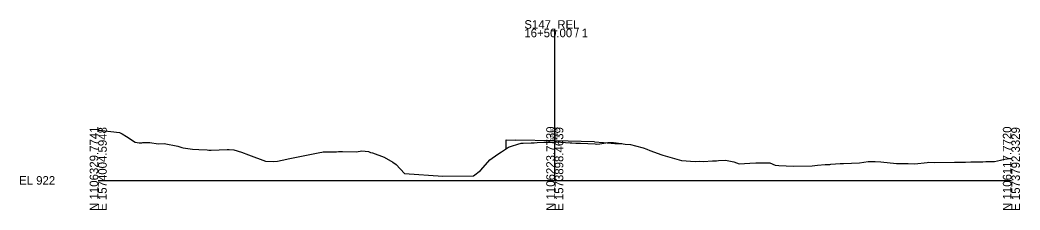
# Model space of a CAD drawing. Extents: x 1557985 to 1558314, y 1113650 to 1118205.
# Drawn here: x 1557985.4 to 1558314, y 1114650.1 to 1114712.4 of the extents above; entities that cross this region are included whole.
import ezdxf

# ---------------------------------------------------------------- set-up
doc = ezdxf.new("R2010")
doc.units = 0
for name, color, linetype in [('RD_GPK_XS_Cell', 7, 'Continuous'), ('RD_XS_EarthShd', 7, 'Continuous'), ('RD_XS_ExGround', 7, 'Continuous'), ('RD_XS_Pave', 7, 'Continuous'), ('RD_XS_TieSlope', 7, 'Continuous'), ('RD_XS_TX_Elev_EX', 7, 'Continuous'), ('RD_XS_TX_Elev_PR', 7, 'Continuous')]:
    doc.layers.add(name, color=color, linetype=linetype)

msp = doc.modelspace()

# ---------------------------------------------------------------- linework, layer by layer
at = {"layer": 'RD_GPK_XS_Cell'}
for p, q in [((1558161.13, 1114659.8), (1558161.13, 1114709.55)), ((1558011.13, 1114659.8), (1558161.13, 1114659.8)), ((1558161.13, 1114659.8), (1558311.13, 1114659.8))]:
    msp.add_line(p, q, dxfattribs=at)
at = {"layer": 'RD_XS_EarthShd'}
for p, q in [((1558145.12, 1114673.06), (1558148.13, 1114673)), ((1558174.13, 1114672.48), (1558177.13, 1114672.24)), ((1558177.13, 1114672.24), (1558180.88, 1114671.94))]:
    msp.add_line(p, q, dxfattribs=at)
at = {"layer": 'RD_XS_ExGround'}
msp.add_lwpolyline([(1558011.13, 1114676.38), (1558011.45, 1114676.32), (1558018.08, 1114675.46), (1558018.99, 1114675.08), (1558020.46, 1114674.21), (1558023.22, 1114672.32), (1558024.54, 1114672.07), (1558025.44, 1114672.14), (1558025.82, 1114672.19), (1558028.04, 1114672.23), (1558030.83, 1114671.78), (1558032.84, 1114671.91), (1558037.34, 1114671.01), (1558038.25, 1114670.67), (1558038.58, 1114670.58), (1558039, 1114670.53), (1558042.11, 1114670.08), (1558044.19, 1114669.96), (1558046.96, 1114669.8), (1558047.46, 1114669.69), (1558048.25, 1114669.69), (1558050.92, 1114669.82), (1558053.51, 1114669.9), (1558054.1, 1114669.89), (1558055.69, 1114669.86), (1558058.18, 1114669.06), (1558060.55, 1114668.17), (1558066.05, 1114666.15), (1558068.66, 1114666.05), (1558070.05, 1114666.12), (1558071.51, 1114666.41), (1558074.05, 1114666.97), (1558083.9, 1114668.95), (1558084.59, 1114669.1), (1558085.07, 1114669.16), (1558086.25, 1114669.18), (1558088.84, 1114669.19), (1558089.45, 1114669.19), (1558090.08, 1114669.24), (1558091.35, 1114669.3), (1558096.01, 1114669.17), (1558097.73, 1114669.45), (1558099.97, 1114669.25), (1558100.56, 1114668.97), (1558101.23, 1114668.87), (1558105.09, 1114667.42), (1558107.93, 1114665.74), (1558108.97, 1114665.04), (1558111.71, 1114662.06), (1558124.31, 1114661.2), (1558134.44, 1114661.3), (1558136.7, 1114663.05), (1558139.1, 1114665.79), (1558139.75, 1114666.49), (1558142.41, 1114668.41), (1558143.58, 1114669.17), (1558145.95, 1114670.71), (1558146.96, 1114671.06), (1558148.94, 1114671.66), (1558150.05, 1114672.02), (1558150.71, 1114672.04), (1558153.32, 1114672.11), (1558154.35, 1114672.15), (1558155.32, 1114672.2), (1558157.52, 1114672.34), (1558158.42, 1114672.37), (1558160.06, 1114672.38), (1558161.13, 1114672.4), (1558161.58, 1114672.41), (1558166.22, 1114672.12), (1558166.68, 1114672.09), (1558168.05, 1114672.03), (1558168.89, 1114672), (1558169.55, 1114671.97), (1558174.37, 1114671.79), (1558174.97, 1114671.73), (1558175.88, 1114671.78), (1558178.58, 1114672.25), (1558180.42, 1114672.24), (1558182.99, 1114671.93), (1558184.27, 1114671.69), (1558185.97, 1114671.53), (1558187.68, 1114671.1), (1558190.14, 1114670.44), (1558191.42, 1114670.04), (1558192.34, 1114669.57), (1558196.31, 1114668.14), (1558196.61, 1114668.11), (1558202.77, 1114666.36), (1558207.27, 1114666), (1558208.73, 1114666.13), (1558209.97, 1114666), (1558212.9, 1114666.23), (1558214.26, 1114666.24), (1558214.93, 1114666.32), (1558217.17, 1114666.46), (1558219.92, 1114665.88), (1558220.83, 1114665.58), (1558221.67, 1114665.26), (1558225.26, 1114665.46), (1558227.15, 1114665.51), (1558231.79, 1114665.61), (1558233.58, 1114664.78), (1558234.72, 1114664.74), (1558239.53, 1114664.44), (1558245.68, 1114664.61), (1558247.39, 1114664.79), (1558250.01, 1114664.97), (1558251.51, 1114665.05), (1558251.84, 1114665.08), (1558254.88, 1114665.29), (1558255.95, 1114665.3), (1558261.22, 1114665.54), (1558264.03, 1114665.98), (1558264.49, 1114666.03), (1558266.33, 1114665.97), (1558268.23, 1114665.85), (1558273.34, 1114665.32), (1558277.26, 1114665.3), (1558279.37, 1114665.24), (1558283.46, 1114665.64), (1558284.06, 1114665.73), (1558285.98, 1114665.69), (1558292.41, 1114665.82), (1558294.38, 1114665.74), (1558295.01, 1114665.76), (1558296.09, 1114665.78), (1558297.76, 1114665.84), (1558299.98, 1114665.88), (1558300.89, 1114665.92), (1558301.73, 1114665.93), (1558302.72, 1114665.97), (1558304.34, 1114665.99), (1558305.54, 1114665.98), (1558307.53, 1114666.39), (1558308.96, 1114666.72), (1558311.13, 1114667.07)], dxfattribs=at)
at = {"layer": 'RD_XS_Pave'}
for p, q in [((1558161.13, 1114672.74), (1558148.13, 1114673)), ((1558174.13, 1114672.48), (1558161.13, 1114672.74))]:
    msp.add_line(p, q, dxfattribs=at)
at = {"layer": 'RD_XS_TieSlope'}
for p, q in [((1558145.12, 1114670.17), (1558145.12, 1114673.06)), ((1558180.88, 1114671.94), (1558183.18, 1114671.89))]:
    msp.add_line(p, q, dxfattribs=at)

# ---------------------------------------------------------------- texts
at = {"layer": 'RD_GPK_XS_Cell'}
for s, p in [('S147_REL', (1558151.13, 1114709.55)), ('16+50.00 / 1', (1558151.13, 1114706.75)), ('EL 922', (1557985.13, 1114658.4))]:
    msp.add_text(s, height=2.8, dxfattribs=at).set_placement(p)
for s, p in [('N 1106329.7741', (1558011.13, 1114649.8)), ('E 1574004.5948', (1558013.93, 1114649.8)), ('N 1106223.7730', (1558161.13, 1114649.8)), ('E 1573898.4639', (1558163.93, 1114649.8)), ('N 1106117.7720', (1558311.13, 1114649.8)), ('E 1573792.3329', (1558313.93, 1114649.8))]:
    msp.add_text(s, height=2.8, rotation=90, dxfattribs=at).set_placement(p)
at = {"layer": 'RD_XS_TX_Elev_EX'}
msp.add_text('934.60', height=1, rotation=90, dxfattribs=at).set_placement((1558160.63, 1114672.9))
at = {"layer": 'RD_XS_TX_Elev_PR'}
msp.add_text(' 934.94', height=1, rotation=90, dxfattribs=at).set_placement((1558162.13, 1114672.74))

doc.saveas('drawing.dxf')
